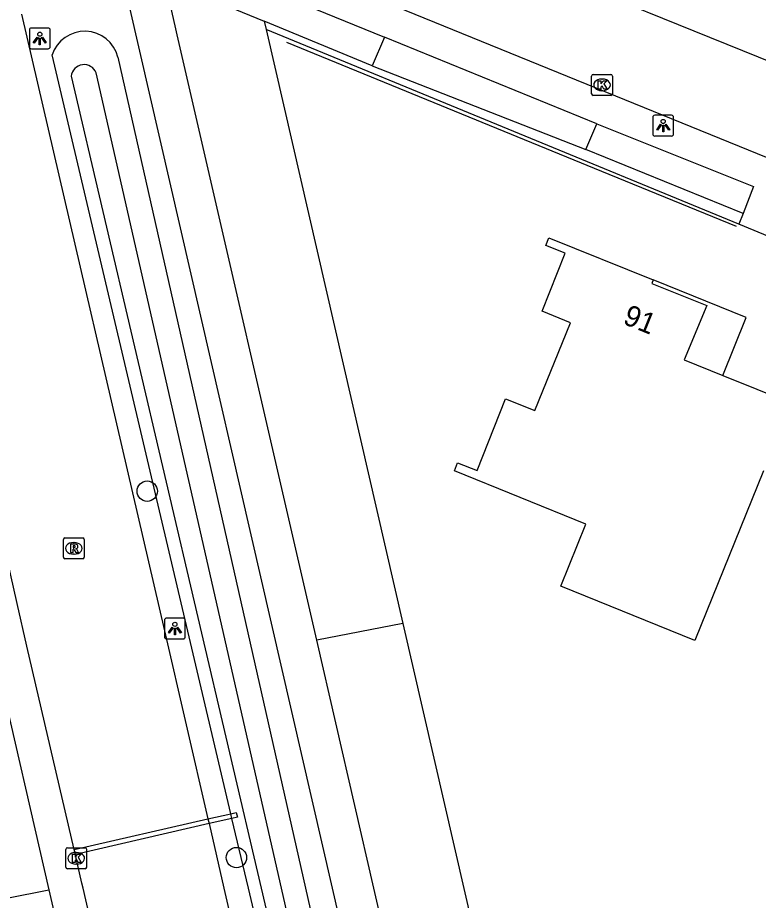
# Model space of a CAD drawing. Extents: x 156414 to 157775, y 382335 to 383765.
# Drawn here: x 156643.83 to 156679.4, y 382999.41 to 383041.78 of the extents above; entities that cross this region are included whole.
import ezdxf

# ---------------------------------------------------------------- set-up
doc = ezdxf.new("R2010")
doc.units = 0
for name, color, linetype in [('IMGEO_Berm_groen', 7, 'Continuous'), ('IMGEO_Boom', 7, 'Continuous'), ('IMGEO_Greppel_droge_sloot', 7, 'Continuous'), ('IMGEO_Groenvoorziening', 7, 'Continuous'), ('IMGEO_Hek', 7, 'Continuous'), ('IMGEO_Kolk', 7, 'Continuous'), ('IMGEO_Lichtpunt', 7, 'Continuous'), ('IMGEO_Lijnafwatering', 7, 'Continuous'), ('IMGEO_Pand', 7, 'Continuous'), ('IMGEO_Pand_nummerreeks', 7, 'Continuous'), ('IMGEO_Pand_overbouw', 7, 'Continuous'), ('IMGEO_Rijbaan_lokaal_gesloten', 7, 'Continuous'), ('IMGEO_Rijbaan_lokaal_open', 7, 'Continuous'), ('IMGEO_Rioolput', 7, 'Continuous'), ('IMGEO_Voetpad_open', 7, 'Continuous')]:
    doc.layers.add(name, color=color, linetype=linetype)

msp = doc.modelspace()

# ---------------------------------------------------------------- linework, layer by layer
at = {"layer": 'IMGEO_Berm_groen'}
for points in [[(156659.227, 382981.695), (156654.913, 383000), (156654.125, 383003.346), (156654.073, 383003.566), (156645.489, 383039.993)], [(156648.651, 383039.881), (156657.656, 383000), (156661.733, 382981.945)]]:
    msp.add_lwpolyline(points, dxfattribs=at)
msp.add_arc((156647.054, 383039.483), 1.646, 13.9888, 161.954, dxfattribs=at)
at = {"layer": 'IMGEO_Boom'}
for centre in [(156650.056, 383019.052), (156654.34, 383001.463)]:
    msp.add_circle(centre, 0.489, dxfattribs=at)
at = {"layer": 'IMGEO_Greppel_droge_sloot'}
for points in [[(156660.35, 382983.054), (156656.499, 383000), (156647.605, 383039.137)], [(156646.406, 383038.974), (156655.532, 383000), (156659.531, 382982.924)]]:
    msp.add_lwpolyline(points, dxfattribs=at)
msp.add_arc((156647.026, 383038.902), 0.624, 22.081, 173.4024, dxfattribs=at)
at = {"layer": 'IMGEO_Groenvoorziening'}
for points in [[(156650.899, 383043.586), (156655.669, 383041.618)], [(156660.862, 383039.476), (156655.669, 383041.618)], [(156655.669, 383041.618), (156655.761, 383041.218)], [(156678.474, 383031.865), (156655.761, 383041.218)], [(156655.761, 383041.218), (156662.329, 383012.702)], [(156678.668, 383032.375), (156671.113, 383035.456)], [(156662.329, 383012.702), (156658.2, 383011.895)], [(156662.329, 383012.702), (156669.262, 382982.597), (156669.34, 382982.26), (156665.247, 382981.316)], [(156639.177, 382998.705), (156645.327, 382999.919)]]:
    msp.add_lwpolyline(points, dxfattribs=at)
at = {"layer": 'IMGEO_Hek'}
for points in [[(156656.741, 383040.612), (156671.878, 383034.408)], [(156671.878, 383034.408), (156678.337, 383031.771)]]:
    msp.add_lwpolyline(points, dxfattribs=at)
at = {"layer": 'IMGEO_Kolk'}
for p, q in [((156671.396, 383038.127), (156671.396, 383038.979)), ((156671.471, 383039.053), (156672.323, 383039.053)), ((156671.884, 383038.833), (156671.909, 383038.833)), ((156672.397, 383038.979), (156672.397, 383038.127)), ((156671.907, 383038.273), (156671.882, 383038.273)), ((156672.323, 383038.053), (156671.471, 383038.053)), ((156646.147, 383001.002), (156646.147, 383001.854)), ((156646.222, 383001.928), (156647.074, 383001.928)), ((156647.148, 383001.854), (156647.148, 383001.002)), ((156646.635, 383001.708), (156646.66, 383001.708)), ((156646.658, 383001.148), (156646.633, 383001.148)), ((156647.074, 383000.928), (156646.222, 383000.928))]:
    msp.add_line(p, q, dxfattribs=at)
for points in [[(156671.396, 383038.127), (156671.396, 383038.979)], [(156671.471, 383039.053), (156672.323, 383039.053)], [(156671.717, 383038.753), (156671.84, 383038.753), (156671.84, 383038.602), (156671.97, 383038.753), (156672.134, 383038.753), (156671.988, 383038.602), (156672.141, 383038.353), (156671.989, 383038.353), (156671.904, 383038.517), (156671.84, 383038.45), (156671.84, 383038.353), (156671.717, 383038.353), (156671.717, 383038.753)], [(156672.397, 383038.979), (156672.397, 383038.127)], [(156672.323, 383038.053), (156671.471, 383038.053)], [(156646.147, 383001.002), (156646.147, 383001.854)], [(156646.222, 383001.928), (156647.074, 383001.928)], [(156647.148, 383001.854), (156647.148, 383001.002)], [(156646.468, 383001.628), (156646.591, 383001.628), (156646.591, 383001.477), (156646.721, 383001.628), (156646.885, 383001.628), (156646.739, 383001.477), (156646.892, 383001.228), (156646.74, 383001.228), (156646.655, 383001.392), (156646.591, 383001.325), (156646.591, 383001.228), (156646.468, 383001.228), (156646.468, 383001.628)], [(156647.074, 383000.928), (156646.222, 383000.928)]]:
    msp.add_lwpolyline(points, dxfattribs=at)
for centre, start, end in [((156671.473, 383038.977), 91.552, 178.448), ((156671.473, 383038.977), 91.552, 178.448), ((156672.321, 383038.977), 1.552, 88.448), ((156672.321, 383038.977), 1.552, 88.448), ((156671.473, 383038.129), 181.552, 268.448), ((156671.473, 383038.129), 181.552, 268.448), ((156672.321, 383038.129), 271.552, 358.448), ((156672.321, 383038.129), 271.552, 358.448), ((156646.224, 383001.852), 91.552, 178.448), ((156646.224, 383001.852), 91.552, 178.448), ((156647.072, 383001.852), 1.552, 88.448), ((156647.072, 383001.852), 1.552, 88.448), ((156646.224, 383001.004), 181.552, 268.448), ((156646.224, 383001.004), 181.552, 268.448), ((156647.072, 383001.004), 271.552, 358.448), ((156647.072, 383001.004), 271.552, 358.448)]:
    msp.add_arc(centre, 0.0765, start, end, dxfattribs=at)
for centre, major_axis, ratio, start_param, end_param in [((156671.883, 383038.553), (-0.387, 0.002), 0.722429, 4.712389, 7.853982), ((156671.908, 383038.553), (-0.39, 0.002), 0.717154, 1.570796, 4.712389), ((156646.634, 383001.428), (-0.387, 0.002), 0.722429, 4.712389, 7.853982), ((156646.659, 383001.428), (-0.39, 0.002), 0.717154, 1.570796, 4.712389)]:
    msp.add_ellipse(centre, major_axis=major_axis, ratio=ratio, start_param=start_param, end_param=end_param, dxfattribs=at)
at = {"layer": 'IMGEO_Lichtpunt'}
for p, q in [((156645.301, 383041.283), (156644.493, 383041.283)), ((156645.301, 383041.283), (156644.493, 383041.283)), ((156644.399, 383041.188), (156644.399, 383040.381)), ((156644.399, 383041.188), (156644.399, 383040.381)), ((156645.395, 383040.381), (156645.395, 383041.188)), ((156645.395, 383040.381), (156645.395, 383041.188)), ((156644.493, 383040.287), (156645.301, 383040.287)), ((156644.493, 383040.287), (156645.301, 383040.287)), ((156674.335, 383037.002), (156674.335, 383036.195)), ((156674.335, 383037.002), (156674.335, 383036.195)), ((156675.237, 383037.097), (156674.429, 383037.097)), ((156675.237, 383037.097), (156674.429, 383037.097)), ((156675.331, 383036.195), (156675.331, 383037.002)), ((156675.331, 383036.195), (156675.331, 383037.002)), ((156674.429, 383036.101), (156675.237, 383036.101)), ((156674.429, 383036.101), (156675.237, 383036.101)), ((156650.885, 383012.862), (156650.885, 383012.055)), ((156650.885, 383012.862), (156650.885, 383012.055)), ((156651.787, 383012.957), (156650.979, 383012.957)), ((156651.787, 383012.957), (156650.979, 383012.957)), ((156651.881, 383012.055), (156651.881, 383012.862)), ((156651.881, 383012.055), (156651.881, 383012.862)), ((156650.979, 383011.961), (156651.787, 383011.961)), ((156650.979, 383011.961), (156651.787, 383011.961))]:
    msp.add_line(p, q, dxfattribs=at)
for points in [[(156644.773, 383040.852), (156644.812, 383040.824), (156644.624, 383040.562), (156644.586, 383040.589), (156644.773, 383040.852)], [(156644.875, 383040.804), (156644.922, 383040.804), (156644.922, 383040.482), (156644.875, 383040.482), (156644.875, 383040.804)], [(156644.985, 383040.824), (156645.023, 383040.851), (156645.21, 383040.589), (156645.171, 383040.561), (156644.985, 383040.824)], [(156674.709, 383036.666), (156674.748, 383036.638), (156674.56, 383036.376), (156674.522, 383036.403), (156674.709, 383036.666)], [(156674.811, 383036.618), (156674.858, 383036.618), (156674.858, 383036.296), (156674.811, 383036.296), (156674.811, 383036.618)], [(156674.921, 383036.638), (156674.959, 383036.665), (156675.146, 383036.403), (156675.107, 383036.375), (156674.921, 383036.638)], [(156651.259, 383012.526), (156651.298, 383012.498), (156651.11, 383012.236), (156651.072, 383012.263), (156651.259, 383012.526)], [(156651.361, 383012.478), (156651.408, 383012.478), (156651.408, 383012.156), (156651.361, 383012.156), (156651.361, 383012.478)], [(156651.471, 383012.498), (156651.509, 383012.525), (156651.696, 383012.263), (156651.657, 383012.235), (156651.471, 383012.498)]]:
    msp.add_lwpolyline(points, dxfattribs=at)
for centre in [(156644.898, 383040.986), (156674.834, 383036.8), (156651.384, 383012.66)]:
    msp.add_circle(centre, 0.0994, dxfattribs=at)
for centre, start, end in [((156644.493, 383041.188), 90, 180), ((156644.493, 383041.188), 90, 180), ((156645.301, 383041.188), 0, 90), ((156645.301, 383041.188), 0, 90), ((156644.493, 383040.381), 180, 270), ((156644.493, 383040.381), 180, 270), ((156645.301, 383040.381), 270, 0), ((156645.301, 383040.381), 270, 360), ((156674.429, 383037.002), 90, 180), ((156674.429, 383037.002), 90, 180), ((156675.237, 383037.002), 0, 90), ((156675.237, 383037.002), 0, 90), ((156674.429, 383036.195), 180, 270), ((156674.429, 383036.195), 180, 270), ((156675.237, 383036.195), 270, 0), ((156675.237, 383036.195), 270, 360), ((156650.979, 383012.862), 90, 180), ((156650.979, 383012.862), 90, 180), ((156651.787, 383012.862), 0, 90), ((156651.787, 383012.862), 0, 90), ((156650.979, 383012.055), 180, 270), ((156650.979, 383012.055), 180, 270), ((156651.787, 383012.055), 270, 0), ((156651.787, 383012.055), 270, 360)]:
    msp.add_arc(centre, 0.0946, start, end, dxfattribs=at)
at = {"layer": 'IMGEO_Lijnafwatering'}
msp.add_lwpolyline([(156646.551, 383001.849), (156652.974, 383003.315), (156654.073, 383003.566), (156654.335, 383003.626), (156654.387, 383003.407), (156654.125, 383003.346), (156653.025, 383003.092), (156646.607, 383001.609)], dxfattribs=at)
at = {"layer": 'IMGEO_Pand'}
msp.add_lwpolyline([(156679.645, 383020.034), (156676.35, 383011.881), (156669.914, 383014.496), (156671.116, 383017.474), (156664.811, 383020.027), (156664.964, 383020.411), (156665.893, 383020.042), (156667.265, 383023.486), (156668.673, 383022.927), (156670.383, 383027.138), (156669.018, 383027.698), (156670.132, 383030.474), (156669.205, 383030.84), (156669.342, 383031.209), (156674.355, 383029.195), (156674.291, 383029.025), (156676.922, 383027.964), (156675.845, 383025.353), (156677.699, 383024.606), (156680.962, 383023.292)], dxfattribs=at)
at = {"layer": 'IMGEO_Pand_overbouw'}
msp.add_lwpolyline([(156674.355, 383029.195), (156674.291, 383029.025), (156676.922, 383027.964), (156675.845, 383025.353), (156677.699, 383024.606), (156678.814, 383027.396)], close=True, dxfattribs=at)
at = {"layer": 'IMGEO_Rijbaan_lokaal_gesloten'}
for points in [[(156651.486, 382980.367), (156651.224, 382981.47), (156646.976, 383000), (156646.922, 383000.234), (156646.649, 383001.428), (156646.607, 383001.609), (156646.551, 383001.849), (156644.272, 383011.609), (156643.811, 383013.659), (156642.727, 383018.429), (156639.023, 383034.52), (156635.523, 383049.531), (156634.923, 383052.22), (156634.268, 383055.05), (156634.207, 383055.298)], [(156644.023, 383041.946), (156650.887, 383012.346), (156652.974, 383003.315), (156653.025, 383003.092), (156653.74, 383000), (156657.677, 382982.964), (156658.537, 382979.142), (156658.963, 382977.351), (156659.5, 382975.096)]]:
    msp.add_lwpolyline(points, dxfattribs=at)
at = {"layer": 'IMGEO_Rijbaan_lokaal_open'}
for points in [[(156793.034, 383001.23), (156780.193, 383004.665), (156764.546, 383008.977), (156762.167, 383009.62), (156735.088, 383017.425), (156694.029, 383033.976), (156654.02, 383050.165)], [(156757.494, 383006.379), (156733.896, 383013.266), (156689.001, 383031.323), (156650.109, 383047.168)]]:
    msp.add_lwpolyline(points, dxfattribs=at)
at = {"layer": 'IMGEO_Rioolput'}
for p, q in [((156646.031, 383015.88), (156646.031, 383016.732)), ((156646.106, 383016.806), (156646.958, 383016.806)), ((156647.032, 383016.732), (156647.032, 383015.88)), ((156646.519, 383016.586), (156646.544, 383016.586)), ((156646.958, 383015.806), (156646.106, 383015.806)), ((156646.542, 383016.026), (156646.517, 383016.026))]:
    msp.add_line(p, q, dxfattribs=at)
for points in [[(156646.031, 383015.88), (156646.031, 383016.732)], [(156646.106, 383016.806), (156646.958, 383016.806)], [(156647.032, 383016.732), (156647.032, 383015.88)], [(156646.62, 383016.504), (156646.368, 383016.506), (156646.368, 383016.106)], [(156646.368, 383016.106), (156646.492, 383016.106), (156646.492, 383016.268), (156646.503, 383016.268)], [(156646.546, 383016.425), (156646.492, 383016.425), (156646.492, 383016.344)], [(156646.492, 383016.344), (156646.544, 383016.344)], [(156646.55, 383016.239), (156646.621, 383016.106), (156646.761, 383016.106), (156646.696, 383016.232)], [(156646.958, 383015.806), (156646.106, 383015.806)]]:
    msp.add_lwpolyline(points, dxfattribs=at)
for centre, radius, start, end in [((156646.108, 383016.73), 0.0765, 91.552, 178.448), ((156646.108, 383016.73), 0.0765, 91.552, 178.448), ((156646.956, 383016.73), 0.0765, 1.552, 88.448), ((156646.956, 383016.73), 0.0765, 1.552, 88.448), ((156646.502, 383016.215), 0.0533, 26.0293, 88.6989), ((156646.528, 383016.533), 0.19, 274.7715, 282.9687), ((156646.552, 383016.329), 0.0964, 77.0061, 93.1865), ((156646.566, 383016.386), 0.0378, 276.6634, 79.6772), ((156646.619, 383016.394), 0.109, 350.3612, 89.416), ((156646.617, 383016.394), 0.112, 277.5842, 350.9817), ((156646.601, 383016.179), 0.108, 29.5134, 73.7905), ((156646.108, 383015.882), 0.0765, 181.552, 268.448), ((156646.108, 383015.882), 0.0765, 181.552, 268.448), ((156646.956, 383015.882), 0.0765, 271.552, 358.448), ((156646.956, 383015.882), 0.0765, 271.552, 358.448)]:
    msp.add_arc(centre, radius, start, end, dxfattribs=at)
for centre, major_axis, ratio, start_param, end_param in [((156646.518, 383016.306), (-0.387, 0.002), 0.722429, 4.712389, 7.853982), ((156646.543, 383016.306), (-0.39, 0.002), 0.717154, 1.570796, 4.712389)]:
    msp.add_ellipse(centre, major_axis=major_axis, ratio=ratio, start_param=start_param, end_param=end_param, dxfattribs=at)
at = {"layer": 'IMGEO_Voetpad_open'}
for points in [[(156648.498, 383045.327), (156648.705, 383044.428), (156658.933, 383000), (156663.468, 382980.302), (156663.89, 382978.495), (156664.983, 382973.825), (156659.5, 382975.096)], [(156650.512, 383045.296), (156655.265, 383043.374), (156661.453, 383040.839)], [(156658.2, 383011.895), (156651.502, 383040.956), (156651.397, 383041.385), (156650.899, 383043.586)], [(156661.453, 383040.839), (156660.862, 383039.476)], [(156671.643, 383036.684), (156661.453, 383040.839)], [(156660.862, 383039.476), (156671.113, 383035.456)], [(156671.113, 383035.456), (156671.643, 383036.684)], [(156671.643, 383036.684), (156679.163, 383033.677), (156678.668, 383032.375)], [(156678.668, 383032.375), (156678.474, 383031.865)], [(156683.537, 383029.78), (156678.474, 383031.865)], [(156665.247, 382981.316), (156660.941, 383000), (156658.2, 383011.895)], [(156642.802, 383010.851), (156645.327, 382999.919)], [(156645.327, 382999.919), (156650.043, 382979.495)]]:
    msp.add_lwpolyline(points, dxfattribs=at)

# ---------------------------------------------------------------- texts
at = {"layer": 'IMGEO_Pand_nummerreeks'}
msp.add_text('91', height=1, rotation=337.9125, dxfattribs=at).set_placement((156672.847, 383027.11))

doc.saveas('drawing.dxf')
